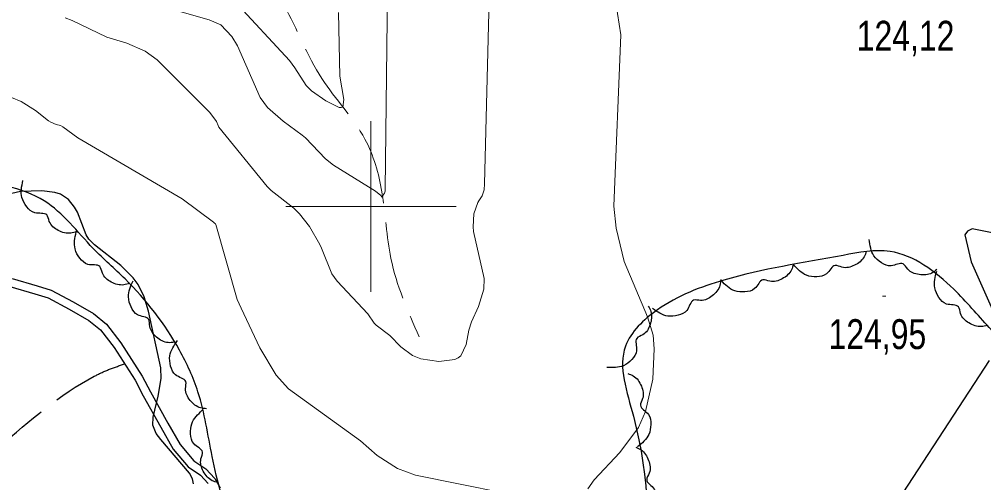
# Model space of a CAD drawing. Extents: x 483843 to 488449, y 4381269 to 4384483.
# Drawn here: x 485396.9 to 485679.6, y 4382919.1 to 4383054.9 of the extents above; entities that cross this region are included whole.
import ezdxf

# ---------------------------------------------------------------- set-up
doc = ezdxf.new("R2010")
doc.units = 0
doc.header["$LTSCALE"] = 3.8
doc.linetypes.add('LONG_DASHED', pattern=[7.5, 6, -1.5])
doc.linetypes.add('MEDIUM_DASHED', pattern=[4.5, 3, -1.5])
for name, color, linetype, lineweight in [('1', 7, 'Continuous', 13), ('15', 7, 'LONG_DASHED', 13), ('27', 7, 'Continuous', 25), ('38', 7, 'Continuous', 25), ('7', 7, 'Continuous', 13), ('8', 7, 'Continuous', 25), ('9', 7, 'Continuous', 13)]:
    doc.layers.add(name, color=color, linetype=linetype, lineweight=lineweight)

msp = doc.modelspace()

# ---------------------------------------------------------------- linework, layer by layer
at = {"layer": '1'}
for p, q in [((485500, 4383025), (485500, 4382975)), ((485475, 4383000), (485525, 4383000))]:
    msp.add_line(p, q, dxfattribs=at)
at = {"layer": '15'}
for points in [[(485400.79, 4383245.56), (485406.29, 4383244.41), (485437.45, 4383238.77), (485468.96, 4383231.4), (485504.33, 4383230.87), (485548.91, 4383220.24), (485591.04, 4383211.58), (485622.86, 4383204.36), (485651.32, 4383198.17), (485680.8, 4383195.25), (485706.08, 4383191.57), (485722.37, 4383193.95), (485735.23, 4383201.55), (485745.53, 4383213.76), (485759.02, 4383234.02), (485775.19, 4383262.78), (485795.18, 4383296.65), (485816.27, 4383323.61), (485841.16, 4383349.54), (485867.84, 4383369.45), (485913.47, 4383388.85), (485935.22, 4383394.97), (485958.89, 4383388.99), (485973.47, 4383381.81), (485979.32, 4383377.07), (485984.47, 4383370.85), (485987.04, 4383362.27), (485987.36, 4383354.02), (485987.36, 4383343.75), (485982.84, 4383337.15), (485969.6, 4383328.73), (485958.55, 4383321.85), (485945.63, 4383309.53), (485931.32, 4383300.15), (485906.76, 4383286.36), (485891.85, 4383276.39), (485880.57, 4383264.12), (485871.36, 4383244.47), (485865.12, 4383222.84), (485860.75, 4383191.43), (485865.12, 4383163.11), (485877.56, 4383143.14), (485893.96, 4383132.18), (485911.26, 4383131.69), (485923.31, 4383135.71), (485933.99, 4383143.04), (485949.29, 4383153.83), (485962.9, 4383167.19), (485985.6, 4383171.87), (486005.81, 4383170.22), (486029.34, 4383160.05), (486043.95, 4383149.41), (486042.89, 4383138.86), (486041.88, 4383131.75), (486041.4, 4383119.4), (486046.63, 4383078.7), (486048.42, 4383062.79), (486056.08, 4383044.24), (486065.61, 4383030.31), (486078.82, 4383011.67), (486095.82, 4382995.68), (486117.1, 4382985.39), (486141.45, 4382970.26), (486161.85, 4382961.49), (486185.85, 4382957.83), (486221.05, 4382956.33), (486256.43, 4382956.62), (486292.45, 4382960.13), (486324.15, 4382965.13)], [(485468.96, 4383231.4), (485460.69, 4383211.27), (485460.2, 4383198), (485460.93, 4383175.7), (485460.86, 4383160.24), (485459.09, 4383147.06), (485455.67, 4383133.31), (485454.08, 4383127.48), (485451.99, 4383122.7), (485447.85, 4383116.61), (485446.95, 4383111.22), (485446.61, 4383103.5), (485450.56, 4383096.39), (485458.98, 4383086.59), (485466.21, 4383073.2), (485474.56, 4383058.98), (485485.59, 4383037.51), (485498.24, 4383019.77), (485503.2, 4383004.31), (485505.84, 4382984.84), (485514.14, 4382961.84)]]:
    msp.add_spline(points, degree=3, dxfattribs=at)
at = {"layer": '27'}
for points in [[(486286.37, 4382818.73), (486278.04, 4382823.01), (486270.91, 4382827.39), (486261.25, 4382830.52), (486249.55, 4382838.56), (486235.78, 4382853.4), (486208.71, 4382873.4), (486199.54, 4382878.26), (486190.05, 4382880.8), (486172.3, 4382887.23), (486138.6, 4382917.4), (486120.98, 4382941.85), (486113.4, 4382950.11), (486108.61, 4382953.78), (486094.45, 4382965.01), (486088.77, 4382972.26), (486086.08, 4382975.81), (486076.44, 4382986.75), (486071.81, 4382993.64), (486063.9, 4383007.83), (486054.58, 4383021.85), (486044.87, 4383035.93), (486027.43, 4383037.8), (485933.61, 4382938.44), (485919.77, 4382940.14), (485889.7, 4382939.08), (485839.54, 4382941.26), (485816.75, 4382944.76), (485741.23, 4382929.61), (485713.92, 4382937.9), (485681.19, 4382964.56), (485670.78, 4382975.78), (485652.13, 4382986.85), (485638.34, 4382985.71), (485603.43, 4382978.48), (485583.93, 4382969.73), (485574.59, 4382959.14), (485576.9, 4382938.62), (485580.71, 4382884.66), (485577.11, 4382863.44), (485511.92, 4382842.02), (485496.71, 4382848.88), (485482.18, 4382864.38), (485474.15, 4382877.06), (485456.13, 4382915.83), (485453.46, 4382926.82), (485449.3, 4382945.73), (485443.9, 4382957.94), (485427.92, 4382978.81), (485418.61, 4382987.72), (485404.26, 4383001.65), (485381.54, 4383009.27), (485374.73, 4383011.94)], [(485413.74, 4382992.7), (485412.04, 4382992.21), (485408.33, 4382993.03), (485405.73, 4382995.65), (485404.97, 4382997.56), (485401.47, 4382998.15), (485399.1, 4382999.97), (485397.69, 4383002.65), (485397.97, 4383007.6)], [(485429.26, 4382977.54), (485427.56, 4382977.06), (485423.86, 4382977.91), (485421.27, 4382980.53), (485420.52, 4382982.45), (485417.02, 4382983.07), (485414.67, 4382984.9), (485413.28, 4382987.59), (485413.58, 4382992.54)], [(485665.84, 4382981.57), (485664.39, 4382980.53), (485660.63, 4382980.08), (485657.3, 4382981.68), (485655.95, 4382983.23), (485652.45, 4382982.64), (485649.61, 4382983.57), (485647.4, 4382985.62), (485646.01, 4382990.39)], [(485645.15, 4382986.97), (485644.54, 4382985.3), (485641.69, 4382982.8), (485638.04, 4382982.24), (485636.05, 4382982.76), (485633.5, 4382980.28), (485630.64, 4382979.44), (485627.65, 4382979.89), (485623.81, 4382983.03)], [(485623.79, 4382983.15), (485623.25, 4382981.46), (485620.51, 4382978.84), (485616.89, 4382978.12), (485614.88, 4382978.55), (485612.43, 4382975.97), (485609.61, 4382975.01), (485606.6, 4382975.33), (485602.63, 4382978.31)], [(485680.62, 4382965.25), (485678.89, 4382964.86), (485675.25, 4382965.92), (485672.81, 4382968.69), (485672.18, 4382970.64), (485668.71, 4382971.46), (485666.47, 4382973.42), (485665.23, 4382976.18), (485665.82, 4382981.11)], [(485442.35, 4382960.26), (485440.58, 4382960.15), (485437.15, 4382961.78), (485435.19, 4382964.91), (485434.87, 4382966.94), (485431.59, 4382968.3), (485429.69, 4382970.6), (485428.91, 4382973.53), (485430.28, 4382978.29)], [(485602.49, 4382978.68), (485602.26, 4382976.92), (485600.03, 4382973.85), (485596.6, 4382972.5), (485594.54, 4382972.57), (485592.6, 4382969.59), (485589.99, 4382968.15), (485586.97, 4382967.92), (485582.54, 4382970.15)], [(485581.27, 4382970.83), (485582.03, 4382969.23), (485581.81, 4382965.44), (485579.64, 4382962.45), (485577.88, 4382961.4), (485577.85, 4382957.85), (485576.43, 4382955.22), (485574.01, 4382953.4), (485569.08, 4382952.89)], [(485451.84, 4382940.8), (485450.08, 4382941.02), (485447.01, 4382943.25), (485445.66, 4382946.69), (485445.72, 4382948.74), (485442.74, 4382950.68), (485441.29, 4382953.29), (485441.06, 4382956.3), (485443.28, 4382960.74)], [(485575.25, 4382951.11), (485576.89, 4382950.42), (485579.24, 4382947.44), (485579.61, 4382943.76), (485578.99, 4382941.81), (485581.33, 4382939.13), (485582.02, 4382936.22), (485581.42, 4382933.26), (485578.08, 4382929.59)], [(485455.13, 4382919.15), (485453.45, 4382919.71), (485450.86, 4382922.48), (485450.18, 4382926.11), (485450.63, 4382928.11), (485448.07, 4382930.58), (485447.15, 4382933.42), (485447.5, 4382936.42), (485450.52, 4382940.36)], [(485577.59, 4382929.54), (485579.18, 4382928.76), (485581.37, 4382925.66), (485581.54, 4382921.97), (485580.81, 4382920.05), (485583, 4382917.25), (485583.52, 4382914.31), (485582.76, 4382911.38), (485579.23, 4382907.9)]]:
    msp.add_spline(points, degree=3, dxfattribs=at)
at = {"layer": '38'}
msp.add_lwpolyline([(485394.84, 4382978.98), (485402.18, 4382976.79), (485406.3, 4382975.49), (485412.71, 4382972.12), (485418.68, 4382968.67), (485422.49, 4382965.59), (485426.69, 4382960.12), (485432.98, 4382950.36), (485435.39, 4382945.74), (485440.5, 4382936.61), (485444.03, 4382930.34), (485448.09, 4382925.56), (485451.57, 4382923.16), (485454.26, 4382920.34), (485455.8, 4382917.58)], dxfattribs=at)
at = {"layer": '38', "linetype": 'MEDIUM_DASHED'}
msp.add_lwpolyline([(485394.2, 4382976.64), (485401.47, 4382974.48), (485405.36, 4382973.25), (485411.54, 4382970), (485417.31, 4382966.67), (485420.75, 4382963.89), (485424.72, 4382958.73), (485430.88, 4382949.14), (485433.26, 4382944.58), (485438.39, 4382935.42), (485442.04, 4382928.95), (485446.45, 4382923.75), (485450, 4382921.31), (485452.31, 4382918.88)], dxfattribs=at)
at = {"layer": '38', "linetype": 'LONG_DASHED'}
for points in [[(485360.36, 4382997.57), (485356.26, 4382987.81), (485350.92, 4382980.07), (485346.57, 4382958.75), (485350.17, 4382942.09), (485365.12, 4382932.3), (485385.66, 4382912.41), (485389.58, 4382911.57), (485392.22, 4382910.72), (485397.76, 4382906.92), (485405.31, 4382900.22), (485412.35, 4382896.75), (485420.94, 4382886.47), (485426.76, 4382871.04), (485431.32, 4382855.29), (485434.98, 4382848), (485437.91, 4382843.55), (485441.79, 4382840.32), (485468.5, 4382819.26), (485479.09, 4382810.22), (485483.74, 4382806.4), (485499.18, 4382794.37), (485502.87, 4382789.79), (485506.31, 4382777.69), (485508.56, 4382769.1), (485511.98, 4382762.71), (485527.1, 4382747.6), (485535.83, 4382738.08), (485558.17, 4382722.04), (485560.6, 4382720.58), (485564.7, 4382717.58), (485566.02, 4382715.05), (485566.5, 4382709.21), (485567.59, 4382698.65), (485568.56, 4382690.56), (485568.58, 4382681.03)], [(485313.95, 4382882.02), (485315.8, 4382883.4), (485322.13, 4382885.69), (485326.49, 4382885.69), (485331.93, 4382887.51), (485354.16, 4382903.22), (485365.85, 4382908.53), (485373.76, 4382914.82), (485391.2, 4382929.76), (485418.9, 4382950.29), (485423.07, 4382952.24), (485427.77, 4382953.9)]]:
    msp.add_spline(points, degree=3, dxfattribs=at)
at = {"layer": '7'}
msp.add_line((485649.91, 4382973.77), (485650.91, 4382973.77), dxfattribs=at)
at = {"layer": '8'}
for points in [[(485447.95, 4382918.75), (485447.66, 4382920.22), (485446.82, 4382921.9), (485438.39, 4382931.76), (485437.09, 4382933.58), (485436.03, 4382935.94), (485436.14, 4382938.32), (485437.66, 4382944.45), (485438.52, 4382949.66), (485438.45, 4382952.8), (485434.77, 4382969.35), (485433.53, 4382973.57), (485431.8, 4382977.16), (485430.32, 4382979.15), (485426.7, 4382982.75), (485419.01, 4382988.78), (485417.34, 4382990.41), (485416.52, 4382991.75), (485413.95, 4382998.32), (485413.11, 4382999.87), (485411.37, 4383002.1), (485409.02, 4383003.62), (485407.32, 4383004.16), (485403.53, 4383004.58), (485397.27, 4383004.38), (485330.02, 4382988.97)], [(485699.69, 4382988.76), (485676.23, 4382993.45), (485674.84, 4382992.8), (485674.02, 4382991.69), (485675.88, 4382983.8), (485682.15, 4382969.75)], [(485681.14, 4382954.91), (485646.92, 4382902.42)]]:
    msp.add_lwpolyline(points, dxfattribs=at)
at = {"layer": '9'}
for points in [[(485563.54, 4382917.29), (485565.45, 4382920), (485572.9, 4382928), (485578.37, 4382935.32), (485580.48, 4382939.96), (485582.63, 4382949.41), (485583.04, 4382958.37), (485582.7, 4382962.34), (485581.05, 4382967.69), (485574.2, 4382983.92), (485571.84, 4382993.65), (485571.13, 4383000.09), (485573.2, 4383050.28), (485567.4, 4383087.87), (485567.31, 4383092.37), (485569.12, 4383095.04), (485588.7, 4383112.78), (485591.62, 4383114.51), (485593.32, 4383115.15), (485596.54, 4383115.76), (485668.51, 4383104.43), (485689.33, 4383097.6)], [(485420.94, 4383063.74), (485452.56, 4383054.72), (485455.95, 4383053.21), (485459.24, 4383049.8), (485460.9, 4383047.09), (485467.56, 4383031.93), (485469.7, 4383029.02), (485474.29, 4383024.99), (485479.86, 4383020.95), (485480.83, 4383020.09), (485486.68, 4383013.95), (485489.01, 4383012.13), (485501.3, 4383004.51), (485502.87, 4383003.26), (485503.24, 4383002.8), (485503.32, 4383002.75), (485503.38, 4383002.73), (485503.49, 4383002.95), (485503.58, 4383003.37), (485503.67, 4383003.57), (485503.92, 4383003.91), (485504.12, 4383004.51), (485504.13, 4383005.09), (485504.8, 4383063.28)], [(485410.33, 4383055.25), (485412.44, 4383054.55), (485422.57, 4383049.6), (485428.45, 4383047.87), (485433.85, 4383045.48), (485437.3, 4383043.03), (485452.81, 4383027.51), (485454.69, 4383024.9), (485455.17, 4383023.77), (485455.44, 4383023.31), (485469.62, 4383005.88), (485470.77, 4383004.72), (485477.43, 4382999.57), (485479.09, 4382997.9), (485481.99, 4382994.12), (485485.03, 4382988.9), (485485.53, 4382987.83), (485488.53, 4382980.35), (485490.05, 4382978.13), (485499.03, 4382968.63), (485500.94, 4382965.89), (485501.53, 4382965.31), (485505.49, 4382962.24), (485508.75, 4382958.91), (485512.19, 4382956.35), (485514.59, 4382955.42), (485519.84, 4382954.62), (485524.62, 4382955.24), (485525.57, 4382955.71), (485526.36, 4382956.31), (485527.86, 4382959.58), (485528.69, 4382963.8), (485529.49, 4382966.22), (485531.53, 4382970.74), (485533.06, 4382975.77), (485533.13, 4382978.92), (485530.05, 4382992.72), (485529.92, 4382994.04), (485530.19, 4382997.87), (485531.33, 4383001.18), (485531.59, 4383001.72), (485532.54, 4383003.13), (485533.18, 4383004.93), (485533.24, 4383006.63), (485534.67, 4383060.88)], [(485490.47, 4383056.89), (485490.92, 4383038.17), (485492.02, 4383031.39), (485491.77, 4383029.16), (485491.29, 4383029.01), (485490.63, 4383029.06), (485486.77, 4383030.94), (485482.57, 4383033.94), (485480.96, 4383035.42), (485477.72, 4383040.63), (485476.1, 4383042.81), (485459.97, 4383060.13)], [(485394.68, 4383031.99), (485397.51, 4383030.82), (485401.7, 4383028.1), (485405.52, 4383025.09), (485406.15, 4383024.7), (485407.78, 4383024.07), (485409, 4383023.77), (485409.73, 4383023.37), (485414.05, 4383020.14), (485444.69, 4383002.31), (485453.89, 4382995.48), (485454.16, 4382995.15), (485454.39, 4382994.97)], [(485454.39, 4382994.97), (485454.44, 4382994.92), (485454.54, 4382994.79), (485460.8, 4382972.74), (485461.97, 4382970.29), (485467.46, 4382958.59), (485472.17, 4382950.67), (485475.86, 4382946.64), (485496.93, 4382931.4), (485501.79, 4382927.06), (485507.77, 4382923.32), (485513.09, 4382921.36), (485551.81, 4382913.49)]]:
    msp.add_lwpolyline(points, dxfattribs=at)

# ---------------------------------------------------------------- texts
at = {"layer": '7', "width": 0.8}
for s, p in [('124,12', (485642.36, 4383045.66)), ('124,95', (485634.1, 4382958.27))]:
    msp.add_text(s, height=8.75, dxfattribs=at).set_placement(p)

doc.saveas('drawing.dxf')
